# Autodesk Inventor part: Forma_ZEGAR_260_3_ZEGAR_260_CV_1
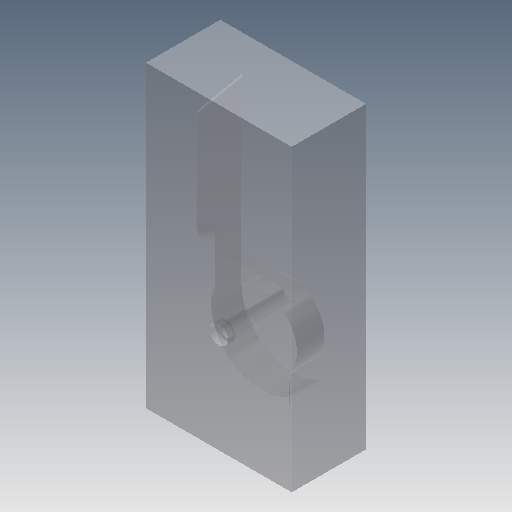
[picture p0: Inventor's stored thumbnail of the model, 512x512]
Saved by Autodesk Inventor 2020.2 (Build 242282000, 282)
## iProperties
Created: 2015-01
Part Number: Forma_ZEGAR_260_3_ZEGAR_260_CV_1
Material: Ogólny
Document SubType Name: Modeling
Designer: F.Stasiak
Density: 1 g/cm^3
Appearance: Domyślna
Catalog Web Link: www.expertbooks.pl
Manager: www.cadconsulting.pl
Company: Fabian Stasiak CAD Consulting
Author: F.Stasiak
Subject: Zbiór ćwiczeń. Autodesk Inventor 2020. Kurs Professional
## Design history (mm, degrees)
node "Forma_ZEGAR_260_3_ZEGAR_260_CV_Base"
feature "Rzeźbienie3"
feature "Bryła1::Forma_ZEGAR_260_3_ZEGAR_260_CV_Base"
tag "Bryła wyprowadzona1"
node "Bryła1"
feature "Forma_ZEGAR_260_3_ZEGAR_260_CV_Base_Bodies"
feature "Powierzchnia3"
body "Srf3"
other parameters: "d0" = 0, "d1" = -26.4075, "d3" = 0, "d4" = -180 deg, "d5" = 0
